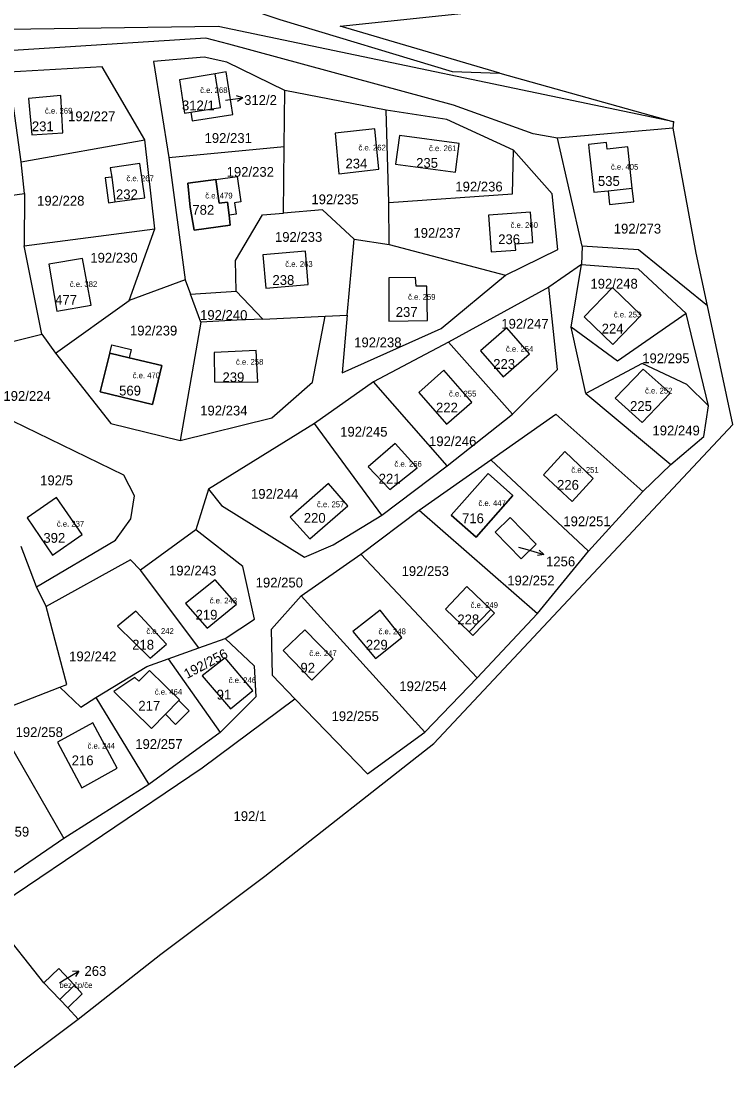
# Model space of a CAD drawing. Extents: x -887272 to -877616, y -1026687 to -1019819.
# Drawn here: x -882079.4 to -881955.8, y -1024195.4 to -1024011.9 of the extents above; entities that cross this region are included whole.
import ezdxf

# ---------------------------------------------------------------- set-up
doc = ezdxf.new("R2010")
doc.units = 0
for name, color, linetype in [('Definiční body', 7, 'Continuous'), ('Hranice parcel', 7, 'Continuous'), ('Parcelní čísla', 7, 'Continuous'), ('Polygon budovy', 7, 'Continuous'), ('Pop  PČ popisy', 7, 'Continuous'), ('Vnitřní kresba', 7, 'Continuous')]:
    doc.layers.add(name, color=color, linetype=linetype)

msp = doc.modelspace()

# ---------------------------------------------------------------- linework, layer by layer
at = {"layer": 'Hranice parcel'}
for p, q in [((-882079.39, -1024036.31), (-882081.54, -1024020.75)), ((-881996.26, -1024020.9), (-881966.06, -1024029.4)), ((-882033.72, -1024033.65), (-882033.62, -1024023.94)), ((-882015.99, -1024027.37), (-882033.62, -1024023.94)), ((-882015.56, -1024043.36), (-882015.99, -1024027.37)), ((-881966.19, -1024030.49), (-881986.24, -1024032.2)), ((-881966.19, -1024030.49), (-881966.06, -1024029.4)), ((-882079.39, -1024036.31), (-882057.94, -1024032.5)), ((-882056.17, -1024047.94), (-882057.94, -1024032.5)), ((-881986.24, -1024032.2), (-881990.45, -1024031.46)), ((-881981.99, -1024050.95), (-881986.24, -1024032.2)), ((-882053.75, -1024035.57), (-882033.72, -1024033.65)), ((-882033.85, -1024045.24), (-882033.72, -1024033.65)), ((-882078.8, -1024041.81), (-882079.39, -1024036.31)), ((-882053.75, -1024035.57), (-882050.91, -1024056.8)), ((-882096.15, -1024044.11), (-882078.8, -1024041.81)), ((-882078.8, -1024041.81), (-882078.85, -1024050.92)), ((-882015.47, -1024050.7), (-882015.56, -1024043.36)), ((-882078.85, -1024050.92), (-882056.17, -1024047.94)), ((-882060.66, -1024060.43), (-882056.17, -1024047.94)), ((-882075.8, -1024066.27), (-882078.85, -1024050.92)), ((-882022.76, -1024062.97), (-882021.57, -1024049.73)), ((-882021.57, -1024049.73), (-882015.47, -1024050.7)), ((-882015.47, -1024050.7), (-881995.27, -1024056.03)), ((-881981.99, -1024050.95), (-881982.11, -1024054.18)), ((-881982.11, -1024054.18), (-881987.76, -1024058.08)), ((-881983.9, -1024065.01), (-881982.11, -1024054.18)), ((-882050.91, -1024056.8), (-882060.66, -1024060.43)), ((-882050.91, -1024056.8), (-882049.97, -1024059.33)), ((-881987.76, -1024058.08), (-882005.18, -1024067.63)), ((-882073.41, -1024069.57), (-882060.66, -1024060.43)), ((-882049.97, -1024059.33), (-882042.04, -1024058.8)), ((-882048.19, -1024064.15), (-882049.97, -1024059.33)), ((-882042.04, -1024058.8), (-882037.42, -1024063.65)), ((-882048.19, -1024064.15), (-882051.8, -1024084.74)), ((-882037.42, -1024063.65), (-882026.59, -1024063.12)), ((-882026.59, -1024063.12), (-882022.76, -1024062.97)), ((-881960.02, -1024078.69), (-881963.91, -1024062.69)), ((-881981.34, -1024076.58), (-881983.9, -1024065.01)), ((-882075.8, -1024066.27), (-882073.41, -1024069.57)), ((-882005.18, -1024067.63), (-882018.18, -1024074.54)), ((-881994.05, -1024080.12), (-882005.18, -1024067.63)), ((-882018.18, -1024074.54), (-882028.47, -1024081.74)), ((-882005.43, -1024089.12), (-882018.18, -1024074.54)), ((-881981.34, -1024076.58), (-881966.56, -1024088.9)), ((-882005.43, -1024089.12), (-881994.05, -1024080.12)), ((-882028.47, -1024081.74), (-882046.83, -1024093.16)), ((-882016.75, -1024097.7), (-882028.47, -1024081.74)), ((-882016.75, -1024097.7), (-882005.43, -1024089.12)), ((-882010.27, -1024096.8), (-881997.83, -1024088.08)), ((-881997.83, -1024088.08), (-881980.86, -1024103.94)), ((-881971.46, -1024093.55), (-881966.56, -1024088.9)), ((-882046.83, -1024093.16), (-882049.06, -1024100.21)), ((-881980.86, -1024103.94), (-881971.46, -1024093.55)), ((-882020.4, -1024104.47), (-882010.27, -1024096.8)), ((-882010.27, -1024096.8), (-881989.7, -1024114.76)), ((-882049.06, -1024100.21), (-882058.69, -1024107.22)), ((-882076.7, -1024110.12), (-882079.4, -1024103.11)), ((-882030.77, -1024111.71), (-882020.4, -1024104.47)), ((-882020.4, -1024104.47), (-882000.18, -1024125.91)), ((-881989.7, -1024114.76), (-881980.86, -1024103.94)), ((-882048.55, -1024120.72), (-882058.69, -1024107.22)), ((-882075.03, -1024113.55), (-882076.7, -1024110.12)), ((-882030.77, -1024111.71), (-882009.31, -1024135.36)), ((-882000.18, -1024125.91), (-881989.7, -1024114.76)), ((-882048.55, -1024120.72), (-882043.95, -1024119.08)), ((-882053.87, -1024122.61), (-882048.55, -1024120.72)), ((-882053.87, -1024122.61), (-882044.82, -1024135.41)), ((-882009.31, -1024135.36), (-882000.18, -1024125.91)), ((-882084.49, -1024132.15), (-882072.69, -1024127.57)), ((-882066.44, -1024129.33), (-882057.24, -1024144.48)), ((-882044.82, -1024135.41), (-882057.24, -1024144.48)), ((-882081.79, -1024136.83), (-882071.96, -1024153.83)), ((-882057.24, -1024144.48), (-882071.96, -1024153.83)), ((-882075.46, -1024178.88), (-882085.12, -1024166.68)), ((-882069.52, -1024185.2), (-882071.31, -1024183.21)), ((-882083.16, -1024195.4), (-882069.52, -1024185.2))]:
    msp.add_line(p, q, dxfattribs=at)
for points in [[(-882138.72, -1024014.17), (-882125.55, -1024011.67), (-882085.96, -1024002.08), (-882063.17, -1024001.87), (-882034.49, -1024011.62), (-882004.55, -1024020.66), (-881996.26, -1024020.9)], [(-881996.26, -1024020.9), (-882024.01, -1024012.79), (-881998.04, -1024010.02)], [(-881966.06, -1024029.4), (-882045.19, -1024012.84), (-882138.72, -1024014.17)], [(-881990.45, -1024031.46), (-882004.32, -1024026.5), (-882043.3, -1024015.89), (-882047.34, -1024014.83), (-882128.82, -1024020.06), (-882138.81, -1024017.01), (-882141.19, -1024015.69)], [(-882033.62, -1024023.94), (-882043.68, -1024019.01), (-882047.61, -1024018.17), (-882056.43, -1024018.92), (-882053.75, -1024035.57)], [(-882057.94, -1024032.5), (-882065.31, -1024019.82), (-882081.54, -1024020.75)], [(-882045.7, -1024021.02), (-882051.92, -1024022.08), (-882051, -1024027.88), (-882049.91, -1024027.71)], [(-882049.91, -1024027.71), (-882049.7, -1024029.2), (-882042.62, -1024028.08), (-882043.79, -1024020.69), (-882045.7, -1024021.02)], [(-882049.91, -1024027.71), (-882044.78, -1024026.88), (-882045.7, -1024021.02)], [(-882077.52, -1024031.66), (-882072.14, -1024031.28), (-882072.52, -1024024.8), (-882078.14, -1024025.32), (-882077.52, -1024031.66)], [(-881993.88, -1024034.29), (-882005.45, -1024028.99), (-882015.99, -1024027.37)], [(-882017.26, -1024037.58), (-882017.98, -1024030.61), (-882024.89, -1024031.33), (-882024.21, -1024038.4), (-882017.26, -1024037.58)], [(-881960.2, -1024061.34), (-881962.15, -1024052.19), (-881966.19, -1024030.49)], [(-882003.3, -1024033.17), (-882013.7, -1024031.77), (-882014.37, -1024036.72), (-882003.97, -1024038.12), (-882003.3, -1024033.17)], [(-881977.48, -1024041.35), (-881977.24, -1024043.74), (-881973.01, -1024043.27), (-881973.27, -1024040.88), (-881974.06, -1024033.73), (-881977.61, -1024034.12), (-881977.74, -1024032.98), (-881980.86, -1024033.3), (-881980.74, -1024034.47), (-881979.94, -1024041.62), (-881977.48, -1024041.35)], [(-882015.56, -1024043.36), (-881994.07, -1024041.9), (-881993.88, -1024034.29)], [(-881995.27, -1024056.03), (-881986.22, -1024051.53), (-881987.19, -1024041.89), (-881993.88, -1024034.29)], [(-882063.94, -1024037.39), (-882063.65, -1024038.98), (-882064.79, -1024039.13), (-882064.24, -1024043.45), (-882063.1, -1024043.29), (-882057.94, -1024042.58), (-882058.8, -1024036.64), (-882063.94, -1024037.39)], [(-882050.43, -1024040.02), (-882045.57, -1024039.37), (-882041.87, -1024038.87), (-882041.23, -1024043.27), (-882042.37, -1024043.46), (-882042.05, -1024045.4), (-882043.29, -1024045.59), (-882043.08, -1024047.35), (-882049.32, -1024048.18)], [(-882049.32, -1024048.18), (-882050.05, -1024044.19), (-882050.43, -1024040.02)], [(-882042.04, -1024058.8), (-882042.17, -1024053.44), (-882037.46, -1024045.53), (-882033.85, -1024045.24)], [(-882021.57, -1024049.73), (-882027.06, -1024044.68), (-882033.85, -1024045.24)], [(-881998.24, -1024045.59), (-881997.75, -1024051.95), (-881993.51, -1024051.65), (-881993.59, -1024050.57), (-881990.55, -1024050.36), (-881990.92, -1024045.08), (-881998.24, -1024045.59)], [(-882116.91, -1024046.86), (-882109.08, -1024060.61), (-882091.67, -1024070.17), (-882075.8, -1024066.27)], [(-881960.2, -1024061.34), (-881972.17, -1024051.58), (-881981.99, -1024050.95)], [(-882067.25, -1024061.24), (-882068.72, -1024053.09), (-882074.61, -1024054.11), (-882073.18, -1024062.27), (-882067.25, -1024061.24)], [(-882036.91, -1024058.26), (-882029.54, -1024057.62), (-882030.04, -1024051.84), (-882037.41, -1024052.48), (-882036.91, -1024058.26)], [(-881982.11, -1024054.18), (-881972.27, -1024054.88), (-881963.91, -1024062.69)], [(-882022.76, -1024062.97), (-882023.66, -1024072.94), (-882006.48, -1024065.27), (-881995.27, -1024056.03)], [(-882008.92, -1024057.9), (-882010.82, -1024057.94), (-882010.93, -1024056.44), (-882015.56, -1024056.46), (-882015.54, -1024063.98), (-882008.84, -1024063.9), (-882008.92, -1024057.9)], [(-881994.05, -1024080.12), (-881986.25, -1024072.41), (-881987.76, -1024058.08)], [(-881976.63, -1024068.04), (-881971.73, -1024062.95), (-881976.71, -1024058.15), (-881981.62, -1024063.24), (-881976.63, -1024068.04)], [(-882069.52, -1024185.2), (-882055.12, -1024173.92), (-882037.1, -1024160.36), (-882007.72, -1024137.32), (-881955.8, -1024081.94), (-881960.2, -1024061.34)], [(-882051.8, -1024084.74), (-882035.87, -1024080.78), (-882028.78, -1024074.57), (-882026.59, -1024063.12)], [(-882037.42, -1024063.65), (-882041.92, -1024063.81), (-882048.19, -1024064.15)], [(-881963.91, -1024062.69), (-881975.83, -1024070.92), (-881983.9, -1024065.01)], [(-881999.62, -1024069.16), (-881995.69, -1024073.66), (-881991.13, -1024069.68), (-881995.06, -1024065.18), (-881999.62, -1024069.16)], [(-882073.41, -1024069.57), (-882063.84, -1024081.75), (-882051.8, -1024084.74)], [(-882054.97, -1024071.72), (-882056.61, -1024078.46), (-882065.67, -1024076.24), (-882064.02, -1024069.56), (-882063.62, -1024068.09), (-882060.29, -1024068.89), (-882060.66, -1024070.36), (-882054.97, -1024071.72)], [(-882045.9, -1024069.46), (-882045.8, -1024074.52), (-882038.28, -1024074.56), (-882038.58, -1024069.08), (-882045.9, -1024069.46)], [(-881960.02, -1024078.69), (-881963.78, -1024075), (-881971.54, -1024071.37), (-881981.34, -1024076.58)], [(-882005.51, -1024081.91), (-882001.11, -1024078.05), (-882005.97, -1024072.51), (-882010.35, -1024076.39), (-882005.51, -1024081.91)], [(-881966.68, -1024076.52), (-881971.4, -1024072.34), (-881976.26, -1024077.38), (-881971.57, -1024081.6), (-881966.68, -1024076.52)], [(-882060.37, -1024098.33), (-882059.72, -1024094.32), (-882061.57, -1024090.71), (-882089.45, -1024077.18)], [(-881966.56, -1024088.9), (-881960.82, -1024084.04), (-881960.02, -1024078.69)], [(-881997.83, -1024088.08), (-881986.52, -1024080.15), (-881971.46, -1024093.55)], [(-882010.64, -1024089.46), (-882014.46, -1024085.24), (-882019.12, -1024089.3), (-882015.36, -1024093.24), (-882010.64, -1024089.46)], [(-881980.04, -1024091.29), (-881984.97, -1024086.62), (-881988.71, -1024090.67), (-881983.71, -1024095.29), (-881980.04, -1024091.29)], [(-882000.36, -1024101.52), (-882004.71, -1024097.69), (-881998.28, -1024090.47), (-881994, -1024094.28), (-882000.36, -1024101.52)], [(-882046.83, -1024093.16), (-882044.58, -1024096.03), (-882030.18, -1024104.96), (-882025.22, -1024102.86), (-882016.75, -1024097.7)], [(-882032.69, -1024098.05), (-882029.27, -1024101.79), (-882022.64, -1024096.04), (-882026.02, -1024092.19), (-882032.69, -1024098.05)], [(-882073.92, -1024104.65), (-882068.81, -1024101.06), (-882073.28, -1024094.64), (-882078.36, -1024098.17), (-882073.92, -1024104.65)], [(-882076.7, -1024110.12), (-882062.98, -1024102.04), (-882060.37, -1024098.33)], [(-881997.1, -1024100.62), (-881994.49, -1024098.07), (-881989.95, -1024102.73), (-881992.54, -1024105.27), (-881997.1, -1024100.62)], [(-882043.95, -1024119.08), (-882038.89, -1024115.77), (-882040.92, -1024106.59), (-882049.06, -1024100.21)], [(-882058.69, -1024107.22), (-882060.43, -1024105.42), (-882075.03, -1024113.55)], [(-882041.98, -1024113.14), (-882045.68, -1024108.92), (-882050.86, -1024113.02), (-882047.1, -1024117.32), (-882041.98, -1024113.14)], [(-882031.85, -1024129.56), (-882035.72, -1024125.54), (-882035.9, -1024117.48), (-882030.77, -1024111.71)], [(-881997.83, -1024114.08), (-882001.97, -1024110.09), (-882005.72, -1024113.98), (-882001.58, -1024117.97), (-882000.93, -1024118.6), (-881997.18, -1024114.71), (-881997.83, -1024114.08)], [(-882072.69, -1024127.57), (-882071.47, -1024127.11), (-882075.03, -1024113.55)], [(-882057, -1024122.52), (-882054.16, -1024120.06), (-882059.48, -1024114.34), (-882062.66, -1024116.98), (-882057, -1024122.52)], [(-882013.29, -1024118.9), (-882017.07, -1024114.2), (-882021.79, -1024117.9), (-882017.86, -1024122.57), (-882013.29, -1024118.9)], [(-882043.95, -1024119.08), (-882038.95, -1024123.84), (-882038.66, -1024129.26), (-882044.82, -1024135.41)], [(-882025.21, -1024122.66), (-882030.14, -1024117.57), (-882033.88, -1024121.19), (-882028.94, -1024126.36), (-882025.21, -1024122.66)], [(-882066.44, -1024129.33), (-882057.57, -1024123.99), (-882053.87, -1024122.61)], [(-882043.04, -1024131.32), (-882039.18, -1024128.14), (-882043.94, -1024122.44), (-882047.93, -1024125.57), (-882043.04, -1024131.32)], [(-882050.19, -1024131.68), (-882052, -1024129.85), (-882051.91, -1024129.76), (-882057.08, -1024124.67), (-882058.97, -1024126.52), (-882059.63, -1024125.89), (-882063.31, -1024128.32), (-882056.76, -1024134.74), (-882054.35, -1024132.27), (-882052.57, -1024134.05), (-882050.19, -1024131.68)], [(-882072.69, -1024127.57), (-882069.05, -1024131.01), (-882066.44, -1024129.33)], [(-882082.59, -1024164.97), (-882047.94, -1024141.57), (-882031.85, -1024129.56)], [(-882031.85, -1024129.56), (-882019.27, -1024142.62), (-882009.31, -1024135.36)], [(-882073.08, -1024137.08), (-882068.84, -1024145.04), (-882062.71, -1024141.64), (-882066.97, -1024133.76), (-882073.08, -1024137.08)], [(-882071.96, -1024153.83), (-882083.08, -1024161.39), (-882086.23, -1024160.99), (-882101.79, -1024143.4)], [(-882071.31, -1024183.21), (-882068.78, -1024180.79), (-882070.14, -1024179.33), (-882072.86, -1024176.4), (-882075.46, -1024178.88)], [(-882075.46, -1024178.88), (-882072.69, -1024181.77), (-882071.31, -1024183.21)]]:
    msp.add_lwpolyline(points, dxfattribs=at)
at = {"layer": 'Polygon budovy'}
for points in [[(-882045.7, -1024021.02), (-882051.92, -1024022.08), (-882051, -1024027.88), (-882049.91, -1024027.71), (-882044.78, -1024026.88)], [(-882078.14, -1024025.32), (-882077.52, -1024031.66), (-882072.14, -1024031.28), (-882072.52, -1024024.8)], [(-882017.98, -1024030.61), (-882024.89, -1024031.33), (-882024.21, -1024038.4), (-882017.26, -1024037.58)], [(-882003.3, -1024033.17), (-882013.7, -1024031.77), (-882014.37, -1024036.72), (-882003.97, -1024038.12)], [(-881974.06, -1024033.73), (-881977.61, -1024034.12), (-881977.74, -1024032.98), (-881980.86, -1024033.3), (-881980.74, -1024034.47), (-881979.94, -1024041.62), (-881977.48, -1024041.35), (-881973.27, -1024040.88)], [(-882063.1, -1024043.29), (-882057.94, -1024042.58), (-882058.8, -1024036.64), (-882063.94, -1024037.39), (-882063.65, -1024038.98)], [(-882050.43, -1024040.02), (-882050.05, -1024044.19), (-882049.32, -1024048.18), (-882043.08, -1024047.35), (-882043.29, -1024045.59), (-882043.55, -1024043.33), (-882045.02, -1024043.53), (-882045.57, -1024039.37)], [(-881990.92, -1024045.08), (-881998.24, -1024045.59), (-881997.75, -1024051.95), (-881993.51, -1024051.65), (-881993.59, -1024050.57), (-881990.55, -1024050.36)], [(-882074.61, -1024054.11), (-882073.18, -1024062.27), (-882067.25, -1024061.24), (-882068.72, -1024053.09)], [(-882029.54, -1024057.62), (-882030.04, -1024051.84), (-882037.41, -1024052.48), (-882036.91, -1024058.26)], [(-882010.82, -1024057.94), (-882010.93, -1024056.44), (-882015.56, -1024056.46), (-882015.54, -1024063.98), (-882008.84, -1024063.9), (-882008.92, -1024057.9)], [(-881971.73, -1024062.95), (-881976.71, -1024058.15), (-881981.62, -1024063.24), (-881976.63, -1024068.04)], [(-881991.13, -1024069.68), (-881995.06, -1024065.18), (-881999.62, -1024069.16), (-881995.69, -1024073.66)], [(-882065.67, -1024076.24), (-882056.61, -1024078.46), (-882054.97, -1024071.72), (-882060.66, -1024070.36), (-882064.02, -1024069.56)], [(-882045.9, -1024069.46), (-882045.8, -1024074.52), (-882038.28, -1024074.56), (-882038.58, -1024069.08)], [(-882005.51, -1024081.91), (-882001.11, -1024078.05), (-882005.97, -1024072.51), (-882010.35, -1024076.39)], [(-881966.68, -1024076.52), (-881971.4, -1024072.34), (-881976.26, -1024077.38), (-881971.57, -1024081.6)], [(-882014.46, -1024085.24), (-882019.12, -1024089.3), (-882015.36, -1024093.24), (-882010.64, -1024089.46)], [(-881983.71, -1024095.29), (-881980.04, -1024091.29), (-881984.97, -1024086.62), (-881988.71, -1024090.67)], [(-882004.71, -1024097.69), (-882000.36, -1024101.52), (-881994, -1024094.28), (-881998.28, -1024090.47)], [(-882022.64, -1024096.04), (-882026.02, -1024092.19), (-882032.69, -1024098.05), (-882029.27, -1024101.79)], [(-882073.28, -1024094.64), (-882078.36, -1024098.17), (-882073.92, -1024104.65), (-882068.81, -1024101.06)], [(-882045.68, -1024108.92), (-882050.86, -1024113.02), (-882047.1, -1024117.32), (-882041.98, -1024113.14)], [(-882005.72, -1024113.98), (-882001.58, -1024117.97), (-881997.83, -1024114.08), (-882001.97, -1024110.09)], [(-882059.48, -1024114.34), (-882062.66, -1024116.98), (-882057, -1024122.52), (-882054.16, -1024120.06)], [(-882017.86, -1024122.57), (-882013.29, -1024118.9), (-882017.07, -1024114.2), (-882021.79, -1024117.9)], [(-882033.88, -1024121.19), (-882028.94, -1024126.36), (-882025.21, -1024122.66), (-882030.14, -1024117.57)], [(-882043.94, -1024122.44), (-882047.93, -1024125.57), (-882043.04, -1024131.32), (-882039.18, -1024128.14)], [(-882063.31, -1024128.32), (-882056.76, -1024134.74), (-882054.35, -1024132.27), (-882052, -1024129.85), (-882051.91, -1024129.76), (-882057.08, -1024124.67), (-882058.97, -1024126.52), (-882059.63, -1024125.89)], [(-882066.97, -1024133.76), (-882073.08, -1024137.08), (-882068.84, -1024145.04), (-882062.71, -1024141.64)], [(-882075.46, -1024178.88), (-882072.69, -1024181.77), (-882070.14, -1024179.33), (-882072.86, -1024176.4)]]:
    msp.add_lwpolyline(points, close=True, dxfattribs=at)
at = {"layer": 'Pop  PČ popisy'}
for p, q in [((-882043.93, -1024025.62), (-882043.89, -1024025.61)), ((-882043.89, -1024025.61), (-882040.92, -1024025.19)), ((-882040.92, -1024025.19), (-882041.98, -1024024.84)), ((-882040.92, -1024025.19), (-882041.84, -1024025.83)), ((-881993, -1024103.25), (-881991.51, -1024103.67)), ((-881991.51, -1024103.67), (-881988.62, -1024104.5)), ((-881988.62, -1024104.5), (-881989.73, -1024104.7)), ((-881988.62, -1024104.5), (-881989.45, -1024103.74)), ((-882071.95, -1024178.4), (-882069.38, -1024176.85)), ((-882069.38, -1024176.85), (-882070.49, -1024176.94)), ((-882069.38, -1024176.85), (-882069.98, -1024177.8)), ((-882072.76, -1024178.9), (-882071.95, -1024178.4))]:
    msp.add_line(p, q, dxfattribs=at)
at = {"layer": 'Vnitřní kresba'}
for p, q in [((-882063.65, -1024038.98), (-882063.1, -1024043.29)), ((-882045.57, -1024039.37), (-882045.02, -1024043.53)), ((-881977.48, -1024041.35), (-881973.27, -1024040.88)), ((-882045.02, -1024043.53), (-882043.55, -1024043.33)), ((-882043.55, -1024043.33), (-882043.29, -1024045.59)), ((-882064.02, -1024069.56), (-882060.66, -1024070.36)), ((-881997.83, -1024114.08), (-882001.58, -1024117.97)), ((-882052, -1024129.85), (-882054.35, -1024132.27)), ((-882072.69, -1024181.77), (-882070.14, -1024179.33))]:
    msp.add_line(p, q, dxfattribs=at)

# ---------------------------------------------------------------- texts
at = {"layer": 'Definiční body'}
for s, p in [('č.e. 268', (-882048.31, -1024024.37)), ('č.e. 269', (-882075.26, -1024027.95)), ('č.e. 262', (-882020.82, -1024034.35)), ('č.e. 261', (-882008.57, -1024034.47)), ('č.e. 405', (-881976.98, -1024037.69)), ('č.e. 267', (-882061.11, -1024039.69)), ('č.e. 479', (-882047.43, -1024042.69)), ('č.e. 260', (-881994.41, -1024047.8)), ('č.e. 263', (-882033.53, -1024054.57)), ('č.e. 382', (-882070.94, -1024058.06)), ('č.e. 259', (-882012.2, -1024060.28)), ('č.e. 253', (-881976.47, -1024063.35)), ('č.e. 254', (-881995.21, -1024069.31)), ('č.e. 258', (-882042.09, -1024071.56)), ('č.e. 470', (-882060.03, -1024073.91)), ('č.e. 255', (-882005.1, -1024077.08)), ('č.e. 252', (-881971.05, -1024076.56)), ('č.e. 256', (-882014.57, -1024089.28)), ('č.e. 251', (-881983.86, -1024090.32)), ('č.e. 257', (-882028.03, -1024096.3)), ('č.e. 447', (-881999.98, -1024096.08)), ('č.e. 237', (-882073.2, -1024099.68)), ('č.e. 243', (-882046.65, -1024113.01)), ('č.e. 249', (-882001.35, -1024113.79)), ('č.e. 242', (-882057.64, -1024118.3)), ('č.e. 248', (-882017.34, -1024118.36)), ('č.e. 247', (-882029.35, -1024122.15)), ('č.e. 246', (-882043.35, -1024126.84)), ('č.e. 464', (-882056.19, -1024128.86)), ('č.e. 244', (-882067.87, -1024138.23)), ('bez čp/če', (-882072.74, -1024179.79))]:
    msp.add_text(s, height=1, dxfattribs=at).set_placement(p)
at = {"layer": 'Parcelní čísla'}
for s, p in [('312/1', (-882051.47, -1024027.38)), ('312/2', (-882040.67, -1024026.44)), ('192/227', (-882071.24, -1024029.27)), ('231', (-882077.53, -1024031.01)), ('192/231', (-882047.54, -1024033.04)), ('234', (-882023.07, -1024037.47)), ('235', (-882010.8, -1024037.36)), ('192/232', (-882043.71, -1024038.92)), ('192/236', (-882003.99, -1024041.47)), ('535', (-881979.23, -1024040.51)), ('192/228', (-882076.62, -1024043.93)), ('232', (-882062.92, -1024042.82)), ('192/235', (-882028.99, -1024043.68)), ('782', (-882049.66, -1024045.51)), ('192/273', (-881976.48, -1024048.78)), ('192/233', (-882035.32, -1024050.22)), ('192/237', (-882011.27, -1024049.52)), ('236', (-881996.55, -1024050.62)), ('192/230', (-882067.38, -1024053.83)), ('238', (-882035.75, -1024057.7)), ('192/248', (-881980.53, -1024058.34)), ('477', (-882073.48, -1024061.13)), ('192/240', (-882048.32, -1024063.78)), ('237', (-882014.34, -1024063.25)), ('192/247', (-881996.01, -1024065.3)), ('192/239', (-882060.5, -1024066.48)), ('224', (-881978.58, -1024066.14)), ('192/238', (-882021.56, -1024068.53)), ('192/295', (-881971.54, -1024071.29)), ('223', (-881997.41, -1024072.28)), ('239', (-882044.43, -1024074.58)), ('569', (-882062.38, -1024076.9)), ('192/224', (-882082.47, -1024077.83)), ('192/234', (-882048.3, -1024080.37)), ('222', (-882007.35, -1024079.85)), ('225', (-881973.65, -1024079.58)), ('192/245', (-882023.99, -1024084.05)), ('192/249', (-881969.76, -1024083.83)), ('192/246', (-882008.56, -1024085.69)), ('192/5', (-882076.09, -1024092.49)), ('221', (-882017.3, -1024092.2)), ('226', (-881986.33, -1024093.27)), ('192/244', (-882039.48, -1024094.84)), ('220', (-882030.31, -1024099.01)), ('716', (-882002.83, -1024099.08)), ('192/251', (-881985.24, -1024099.6)), ('392', (-882075.53, -1024102.48)), ('192/243', (-882053.72, -1024108.16)), ('1256', (-881988.24, -1024106.57)), ('192/253', (-882013.33, -1024108.25)), ('192/252', (-881994.98, -1024109.88)), ('192/250', (-882038.67, -1024110.24)), ('219', (-882049.1, -1024115.82)), ('228', (-882003.64, -1024116.64)), ('218', (-882060.11, -1024121.03)), ('229', (-882019.53, -1024121.03)), ('192/242', (-882071.06, -1024123.06)), ('92', (-882030.89, -1024125.03)), ('192/254', (-882013.72, -1024128.24)), ('91', (-882045.45, -1024129.69)), ('217', (-882059.04, -1024131.63)), ('192/255', (-882025.49, -1024133.44)), ('192/258', (-882080.36, -1024136.21)), ('192/257', (-882059.58, -1024138.28)), ('216', (-882070.61, -1024141.12)), ('192/1', (-882042.51, -1024150.8)), ('192/259', (-882086.22, -1024153.5)), ('263', (-882068.39, -1024177.69))]:
    msp.add_text(s, height=1.7, dxfattribs=at).set_placement(p)
msp.add_text('192/256', height=1.7, rotation=28, dxfattribs=at).set_placement((-882050.57, -1024126.14))

doc.saveas('drawing.dxf')
